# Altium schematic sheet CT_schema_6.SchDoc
size 257 x 245 mm
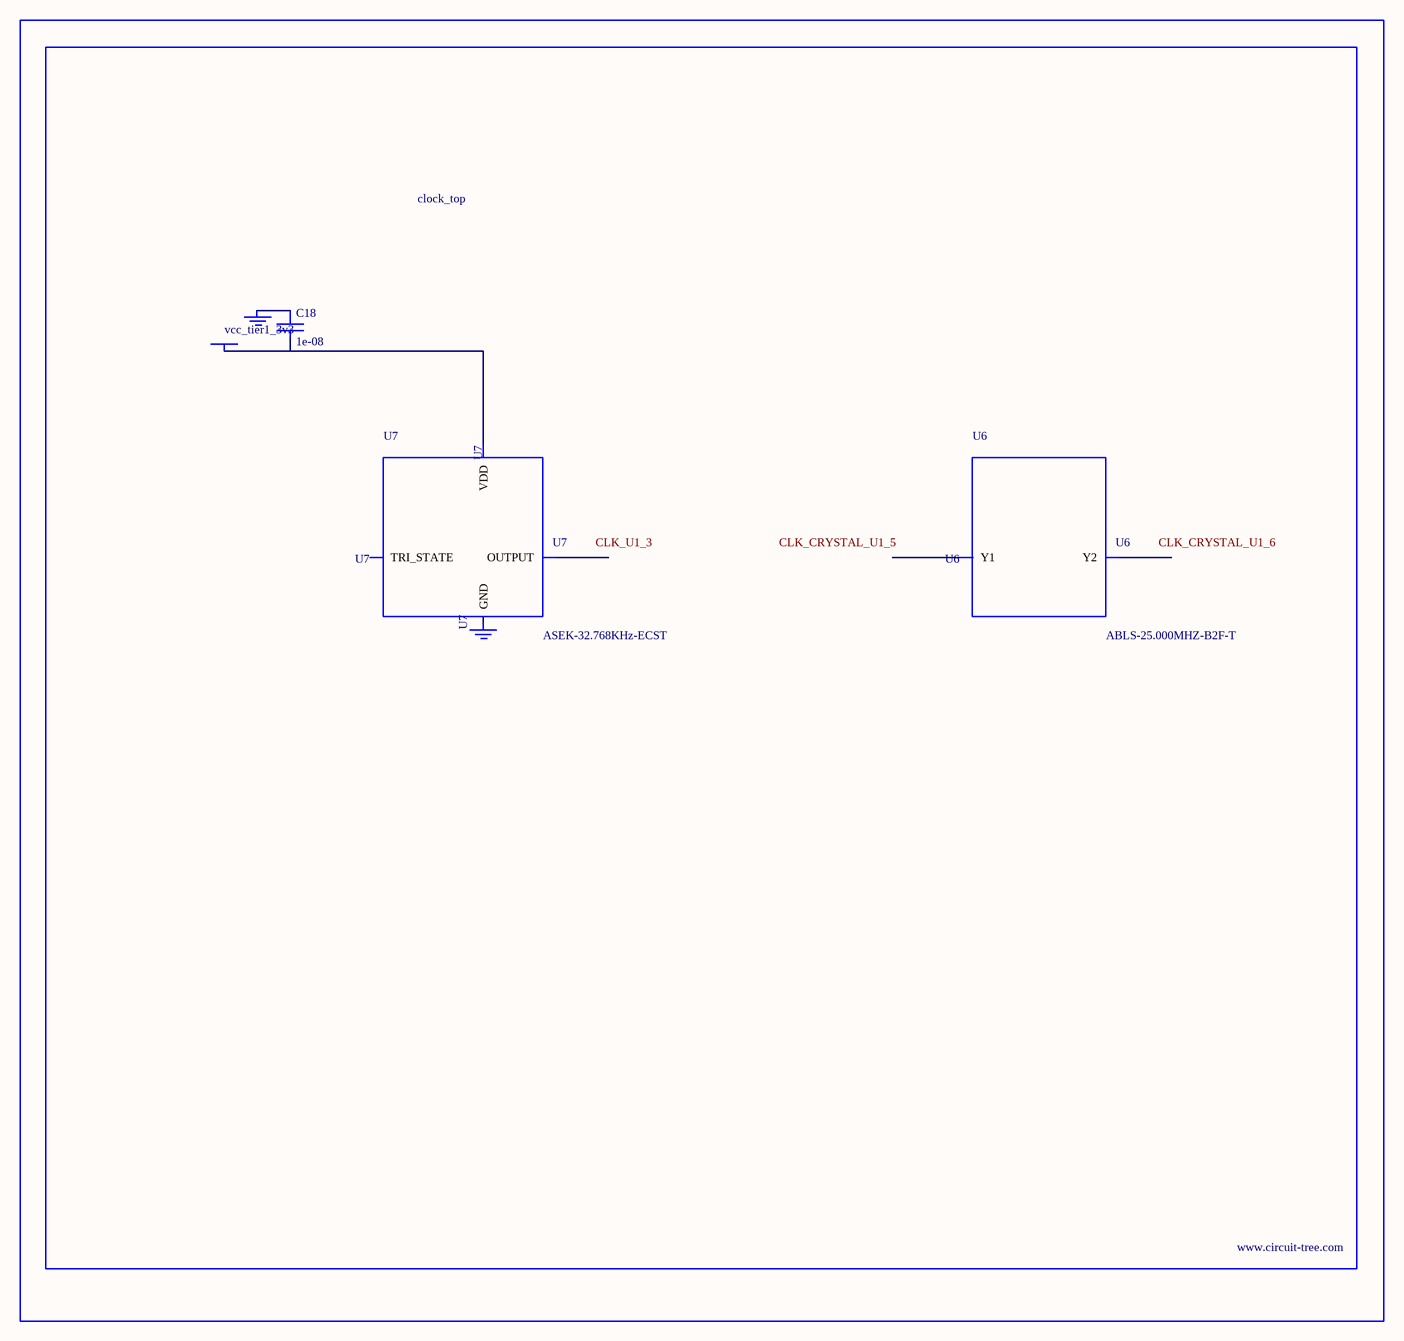
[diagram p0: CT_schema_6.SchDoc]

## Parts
BORDER5  (no value)
C18  1e-08  [C0402]
GND_INSTANCE_5_0  (no value)
GND_INSTANCE_5_1  (no value)
POWER_INSTANCE_5_0  vcc_tier1_3v3
U6  ABLS-25.000MHZ-B2F-T  [ABLS-25.000MHZ-B2F-T]
U7  ASEK-32.768KHz-ECST  [ASEK]

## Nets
NetC18_1: C18.1 GND_INSTANCE_5_0.0(GND)
NetC18_2: C18.2 POWER_INSTANCE_5_0.0(PWR) U7.4(VDD)

Not connected (* = marked no-connect by the designer): GND_INSTANCE_5_1 0(GND); U6 1(Y1) 2(Y2); U7 1(TRI_STATE) 2(GND) 3(OUTPUT)

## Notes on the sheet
- Labels drawn without touching a wire or pin: CLK_CRYSTAL_U1_5, CLK_CRYSTAL_U1_6, CLK_U1_3

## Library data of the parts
BORDER5 = BORDER_PAGE5
C18 = C0402C103K3RAC
GND_INSTANCE_5_0 GND_INSTANCE_5_1 = GND
POWER_INSTANCE_5_0 = PWR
